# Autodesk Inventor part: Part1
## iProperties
Created: 2002-02
Part Number: Part1
Document SubType Name: ﾓﾃﾞﾘﾝｸﾞ
Designer: Administrator
Control State: 0
Master: False
Checked Out: False
Shininess: 64.0
Length Units: 11269
Angle Units: 11279
Time Units: 11290
Mass Units: 11284
Length Display Precision: 2
Angle Display Precision: 1
Density: 0.0
Volumn: 0.0
Area: 0.0
PropertySet Name: Model Information
Author: Administrator
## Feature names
1. 押し出し1 [Extrusion]
2. 押し出し2 [Extrusion]
3. 押し出し3 [Extrusion]
